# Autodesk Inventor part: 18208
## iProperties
Created: 2007-10
Part Number: 18208
Material: 3.2315.71 AlMgSi1 F28
Description: Zentrierring (Al/FPM) DN 40 KF
Document SubType Name: Modellieren
Designer: TMT
Manufacturer: Standard
Standards Organization: Custom
Density: 1 g/cm^3
Vendor: LEYBOLD
Author: TMT
Comments: LEYBOLD
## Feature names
1. Extrusion2
2. Bohrung1 [Hole]
3. Umdrehung1 [Revolution]
4. Umdrehung2 [Revolution]
5. Fase1 [Chamfer]
